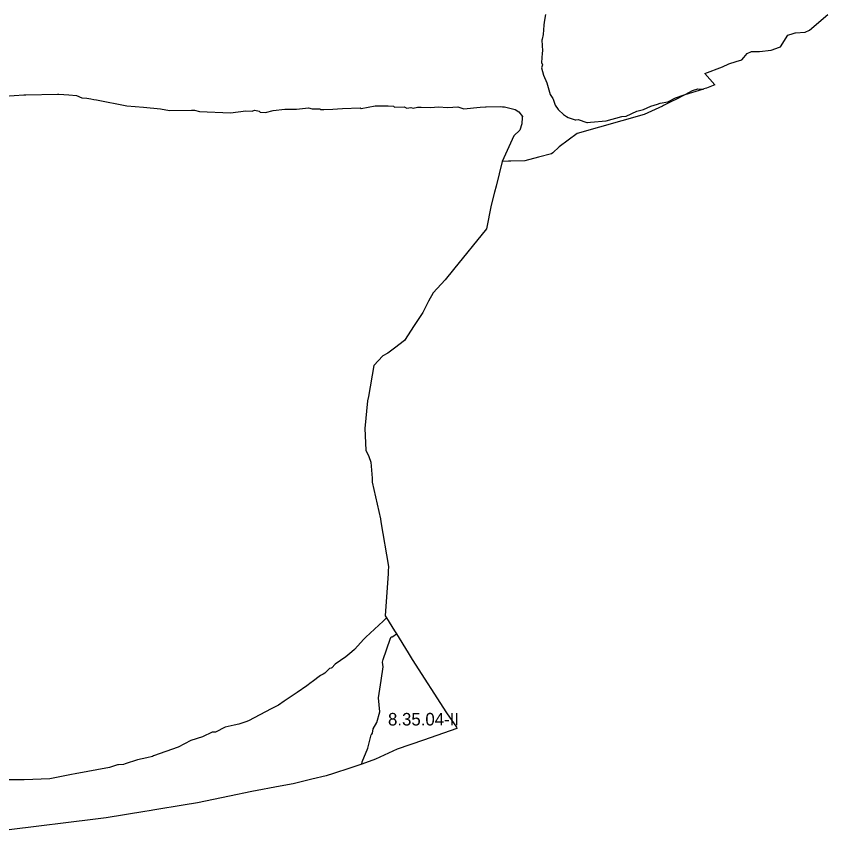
# Model space of a CAD drawing. Extents: x -444937 to -440470, y -1149084 to -1129741.
# Drawn here: x -441707 to -441061, y -1132657 to -1132010 of the extents above; entities that cross this region are included whole.
import ezdxf

# ---------------------------------------------------------------- set-up
doc = ezdxf.new("R2010")
doc.units = 0
doc.layers.add('Vrstva 28', color=7, linetype='Continuous')

msp = doc.modelspace()

# ---------------------------------------------------------------- linework, layer by layer
at = {"layer": 'Vrstva 28'}
for points in [[(-441285.58, -1132008.21), (-441286.67, -1132014.39), (-441287.07, -1132016.71), (-441287.5, -1132024.36), (-441288.39, -1132027.94), (-441288.56, -1132028.61), (-441288.14, -1132037.11), (-441288.32, -1132039.14), (-441288.99, -1132046.46), (-441288.18, -1132048.28), (-441288.77, -1132050.72), (-441287.28, -1132056.67), (-441284.73, -1132062.62), (-441281.97, -1132071.97), (-441279.85, -1132075.16), (-441279.63, -1132075.76), (-441277.97, -1132080.37), (-441277.93, -1132080.47), (-441275.6, -1132083.87), (-441275.12, -1132084.32), (-441271.56, -1132087.71), (-441271.34, -1132087.91), (-441268.95, -1132089.46), (-441267.73, -1132090.25), (-441264.34, -1132091.3), (-441262.08, -1132092), (-441261.57, -1132092.16), (-441259.66, -1132091.95), (-441252.85, -1132094.29), (-441252.26, -1132094.23), (-441250, -1132094.01), (-441237.55, -1132092.8), (-441225.01, -1132089.4), (-441221.4, -1132089.19), (-441212.9, -1132085.15), (-441207.8, -1132083.87), (-441201.85, -1132081.32), (-441196.45, -1132079.63), (-441194.41, -1132078.98), (-441188.24, -1132077.92), (-441182.29, -1132074.52), (-441175.32, -1132072.2), (-441175.12, -1132072.13), (-441174.64, -1132071.97), (-441168.69, -1132068.78), (-441164.44, -1132067.51), (-441160.07, -1132067.69)], [(-441150.99, -1132064.17), (-441158.91, -1132055.25), (-441144.89, -1132050.08), (-441139.79, -1132047.53), (-441133.96, -1132045.71), (-441129.58, -1132044.34), (-441127.94, -1132042.46), (-441125.12, -1132039.24), (-441121.93, -1132037.75), (-441119.73, -1132037.75), (-441115.56, -1132037.75), (-441106.2, -1132036.69), (-441099.45, -1132034.37), (-441098.77, -1132034.14), (-441092.81, -1132024.79), (-441088.6, -1132023.43), (-441087, -1132022.92), (-441086.86, -1132022.87), (-441079, -1132022.45), (-441075.6, -1132020.75), (-441061.15, -1132008.21)], [(-441160.07, -1132067.69), (-441174.91, -1132072.3), (-441182.51, -1132076.1), (-441184.41, -1132077.05), (-441190.24, -1132079.97), (-441191.9, -1132080.8), (-441192.73, -1132081.18), (-441207.3, -1132087.96), (-441260.6, -1132103), (-441274.7, -1132113.6), (-441279.9, -1132118.37), (-441280.8, -1132119.2), (-441291.17, -1132121.91), (-441302, -1132124.75), (-441313.3, -1132124.99), (-441315.17, -1132125.03), (-441320.06, -1132125.14)], [(-441150.99, -1132064.17), (-441157.66, -1132066.94), (-441159.68, -1132067.57), (-441160.07, -1132067.69)], [(-441716.18, -1132073.25), (-441700.78, -1132072.28), (-441699.2, -1132072.18), (-441699.18, -1132072.18), (-441673.97, -1132071.78), (-441672.83, -1132071.76), (-441665.01, -1132072.35), (-441658.8, -1132072.82), (-441654.55, -1132074.52), (-441650.62, -1132074.98), (-441647.32, -1132075.37), (-441645.02, -1132075.82), (-441642.96, -1132076.22), (-441618.84, -1132080.9), (-441605.6, -1132082.16), (-441592.06, -1132083.45)], [(-441592.06, -1132083.45), (-441584.84, -1132084.72), (-441567.24, -1132084.53), (-441564.86, -1132084.51), (-441561.03, -1132085.36), (-441536.38, -1132086.42), (-441524.05, -1132084.93), (-441518.95, -1132085.15), (-441518.63, -1132085.02), (-441516.82, -1132084.3), (-441513.42, -1132085.15), (-441512.57, -1132086), (-441508.32, -1132086.21), (-441502.37, -1132084.72), (-441493.02, -1132083.66), (-441491.69, -1132083.66), (-441487.41, -1132083.66), (-441483.67, -1132083.66), (-441474.32, -1132082.6), (-441471.34, -1132083.34), (-441465.18, -1132083.23), (-441464.54, -1132083.87), (-441464.21, -1132083.87), (-441461.99, -1132083.87), (-441454.75, -1132083.55), (-441451.17, -1132083.39), (-441447.14, -1132083.22), (-441433.09, -1132082.6), (-441432.24, -1132083.02), (-441421.18, -1132080.9), (-441413.54, -1132080.9), (-441410.98, -1132080.9), (-441406.73, -1132081.32), (-441406.7, -1132081.34), (-441405.88, -1132081.96), (-441398.23, -1132081.75), (-441396.1, -1132082.81), (-441392.92, -1132082.17), (-441391, -1132082.81), (-441387.6, -1132081.96), (-441384.68, -1132082.08), (-441376.98, -1132082.38), (-441371.02, -1132081.75), (-441363.37, -1132082.17), (-441355.3, -1132081.75), (-441350.62, -1132083.23), (-441337.63, -1132082.15), (-441333.34, -1132081.79), (-441332.77, -1132081.75), (-441321.72, -1132081.53), (-441319.98, -1132081.64), (-441318.32, -1132081.75), (-441309.81, -1132083.87), (-441306.84, -1132085.78), (-441304.08, -1132089.4), (-441304.15, -1132090.37), (-441304.5, -1132095.35), (-441306.2, -1132100.45), (-441310.91, -1132104.8), (-441320.06, -1132125.14)], [(-441320.06, -1132125.14), (-441325, -1132144.92), (-441326.19, -1132149.68), (-441328.8, -1132160.1), (-441332.58, -1132178.83), (-441358.9, -1132211.25), (-441365.51, -1132219.4), (-441375.15, -1132229.7), (-441378.8, -1132236.35), (-441381.16, -1132240.99), (-441383.31, -1132245.23), (-441390.15, -1132255.67), (-441397.98, -1132267.65), (-441405.92, -1132273.63), (-441411.1, -1132277.8), (-441415.15, -1132279.8), (-441422.28, -1132287.63), (-441426.57, -1132312.13), (-441427.17, -1132315.54), (-441429.5, -1132337.58), (-441428.73, -1132354.89), (-441426.28, -1132359.86), (-441424.64, -1132364.39), (-441423.7, -1132377.22), (-441423.48, -1132380.22), (-441416.99, -1132409.54), (-441416.61, -1132411.77), (-441410.57, -1132447.38), (-441410.83, -1132451.16), (-441410.94, -1132452.83), (-441413.27, -1132486.67), (-441412.3, -1132488.23)], [(-441412.3, -1132488.23), (-441414.79, -1132490.78), (-441428.73, -1132503.49), (-441430.18, -1132505.13), (-441437.55, -1132513.41), (-441439.85, -1132515.36), (-441444.56, -1132519.36), (-441453.06, -1132525.1), (-441455.61, -1132528.07), (-441456.33, -1132528.23), (-441457.53, -1132528.5), (-441458.62, -1132529.66), (-441461.14, -1132532.32), (-441462.55, -1132532.99), (-441464.75, -1132534.02), (-441471.39, -1132539.1), (-441472.02, -1132539.58), (-441475.59, -1132542.31), (-441483.36, -1132547.59), (-441493.61, -1132554.55), (-441498.12, -1132557.62), (-441499.13, -1132558.14), (-441503.36, -1132560.37), (-441503.87, -1132560.64), (-441521.93, -1132570.16), (-441524.07, -1132570.93), (-441529.58, -1132572.92), (-441533.32, -1132573.71), (-441540.63, -1132575.26), (-441548.28, -1132579.08), (-441550.83, -1132579.29), (-441558.48, -1132582.91), (-441567.83, -1132585.67), (-441578.03, -1132590.98), (-441597.57, -1132598.11), (-441598.44, -1132598.42), (-441602.9, -1132599.46), (-441610.34, -1132601.18), (-441620.12, -1132604.38), (-441621.39, -1132604.8), (-441625.35, -1132605.17), (-441625.86, -1132605.22), (-441626.06, -1132605.28), (-441632.45, -1132607.14), (-441659.84, -1132612.34), (-441662.86, -1132612.92), (-441680.05, -1132616.27), (-441700.46, -1132617.13), (-441704.25, -1132617.13), (-441724.26, -1132617.13)], [(-441412.3, -1132488.23), (-441405.81, -1132498.68), (-441404.33, -1132501.07)], [(-441404.33, -1132501.07), (-441395.05, -1132516.01), (-441391.66, -1132521.47), (-441364.49, -1132563.72), (-441356.6, -1132575.22), (-441356.28, -1132576.16), (-441382.8, -1132585.45), (-441403.57, -1132592.72), (-441421.01, -1132600.55), (-441431.86, -1132604.56)], [(-441414.71, -1132527.19), (-441415.46, -1132523.54), (-441414.81, -1132521.27), (-441409.28, -1132505.12), (-441408.43, -1132503.42), (-441407.37, -1132503.21), (-441407.19, -1132503.08), (-441404.33, -1132501.07)], [(-441431.86, -1132604.56), (-441431.6, -1132602.89), (-441426.92, -1132591.83), (-441425.13, -1132584.51), (-441424.37, -1132581.42), (-441423.96, -1132580.85), (-441423.31, -1132579.93), (-441422.67, -1132576.53), (-441419.91, -1132571.43), (-441417.36, -1132562.93), (-441418.63, -1132551.88), (-441416.44, -1132538.09), (-441414.71, -1132527.19)], [(-441431.86, -1132604.56), (-441433.3, -1132605.09), (-441441.27, -1132607.72), (-441454.24, -1132611.99), (-441460.09, -1132613.92), (-441471.63, -1132616.66)], [(-441471.63, -1132616.66), (-441486.5, -1132620.16), (-441496.85, -1132622.15), (-441519.38, -1132626.48), (-441537.12, -1132630.18), (-441562.6, -1132635.5), (-441573.93, -1132637.36), (-441596.48, -1132641.06), (-441601, -1132641.8), (-441604.55, -1132642.39), (-441635.1, -1132647.4), (-441643.57, -1132648.43), (-441712.26, -1132656.77)]]:
    msp.add_lwpolyline(points, dxfattribs=at)

# ---------------------------------------------------------------- texts
msp.add_text('8.35.04-II', height=10, dxfattribs=at).set_placement((-441410.99, -1132573.86))

doc.saveas('drawing.dxf')
